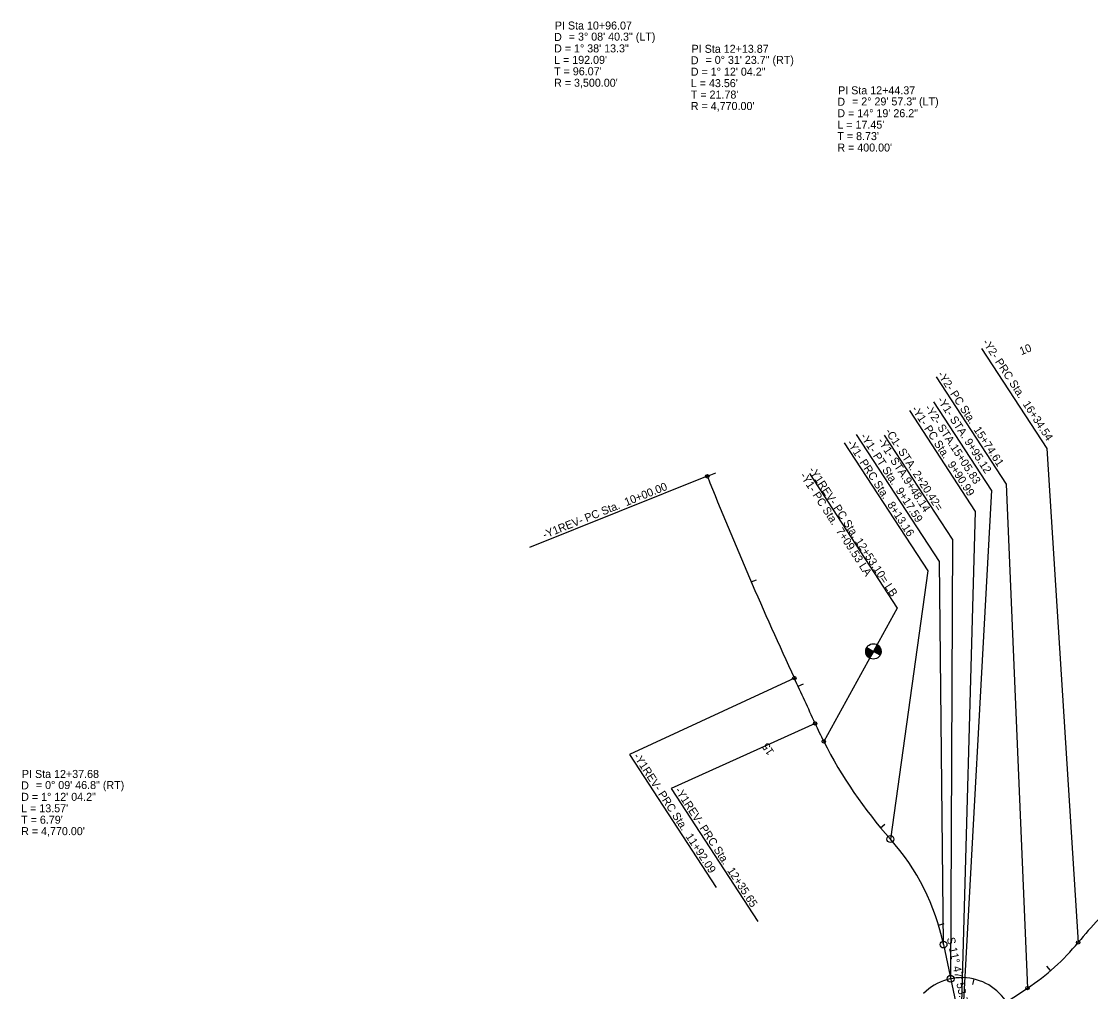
# Model space of a CAD drawing. Extents: x 1636713 to 1642889, y 841520 to 844630.
# Drawn here: x 1639556 to 1640491, y 843782 to 844630 of the extents above; entities that cross this region are included whole.
import ezdxf

# ---------------------------------------------------------------- set-up
doc = ezdxf.new("R2010")
doc.units = 0
for name, color, linetype in [('Exist 4 AWG with gnd feeder circuit in conduit', 7, 'Continuous'), ('Exist 6 AWG with gnd feeder circuit', 7, 'Continuous'), ('Exist 8 AWG with gnd feeder circuit', 7, 'Continuous'), ('Exist 8 AWG with gnd feeder circuit in conduit', 7, 'Continuous'), ('Prop 2 AWG with gnd feeder circuit', 7, 'Continuous'), ('Prop 2 AWG with gnd feeder circuit in conduit', 7, 'Continuous'), ('Prop 4 AWG with gnd feeder circuit', 7, 'Continuous')]:
    doc.layers.add(name, color=color, linetype=linetype)

msp = doc.modelspace()

# ---------------------------------------------------------------- linework, layer by layer
at = {"layer": 'Exist 6 AWG with gnd feeder circuit'}
for p, q in [((1640403.98, 844219.86), (1640353.54, 844297.16)), ((1640369.83, 844176.94), (1640310.39, 844268.03)), ((1640452.2, 844256.33), (1640479.68, 843824.55)), ((1640156.87, 844232.52), (1639999.85, 844169.86)), ((1640416.67, 844225.16), (1640435.28, 843784.64)), ((1640172.29, 844191.74), (1640171.89, 844191.57)), ((1640321.54, 844116.76), (1640257.23, 844000.27)), ((1640300.64, 844078.91), (1640303.93, 844084.77)), ((1640294.79, 844082.19), (1640300.64, 844078.91)), ((1640297.35, 844073.06), (1640300.64, 844078.91)), ((1640300.64, 844078.91), (1640297.35, 844073.06)), ((1640306.5, 844075.63), (1640300.64, 844078.91)), ((1640231.52, 844055.59), (1640087.52, 843988.76)), ((1640249.68, 844016), (1640123.85, 843958.99)), ((1640087.52, 843988.76), (1640163.31, 843872.62)), ((1640123.85, 843958.99), (1640199.63, 843842.85))]:
    msp.add_line(p, q, dxfattribs=at)
for points in [[(1640395.16, 844343.74), (1640452.2, 844256.33)], [(1640355.51, 844318.88), (1640416.67, 844225.16)], [(1640332.21, 844289.39), (1640389.67, 844201.32)], [(1640275.09, 844261.21), (1640348.12, 844149.28), (1640315.45, 843914.9)], [(1640358.34, 844157.37), (1640285.75, 844268.61)], [(1640244.71, 844234.49), (1640321.54, 844116.76)], [(1640403.98, 844219.86), (1640377.83, 843746.81)], [(1640389.67, 844201.32), (1640376.95, 843750.85)], [(1640369.83, 844176.94), (1640368.18, 843792.8)], [(1640361.94, 843822.7), (1640358.34, 844157.37)], [(1640303.98, 844084.74), (1640303.98, 844084.74), (1640300.7, 844078.88)], [(1640304.1, 844084.67), (1640300.81, 844078.82)], [(1640304.21, 844084.6), (1640300.93, 844078.75)], [(1640304.32, 844084.53), (1640301.05, 844078.69)], [(1640304.43, 844084.45), (1640301.16, 844078.62)], [(1640304.54, 844084.37), (1640301.28, 844078.55)], [(1640304.65, 844084.29), (1640301.4, 844078.49)], [(1640304.76, 844084.22), (1640301.52, 844078.42)], [(1640304.87, 844084.14), (1640301.63, 844078.36)], [(1640304.97, 844084.05), (1640301.75, 844078.29)], [(1640305.08, 844083.95), (1640301.87, 844078.23)], [(1640305.18, 844083.86), (1640301.98, 844078.16)], [(1640305.28, 844083.77), (1640302.1, 844078.1)], [(1640305.38, 844083.67), (1640302.22, 844078.03)], [(1640305.48, 844083.57), (1640302.34, 844077.96)], [(1640305.57, 844083.47), (1640302.45, 844077.9)], [(1640305.67, 844083.36), (1640302.57, 844077.83)], [(1640305.77, 844083.26), (1640302.69, 844077.77)], [(1640305.85, 844083.14), (1640302.8, 844077.7)], [(1640305.94, 844083.02), (1640302.92, 844077.64)], [(1640306.03, 844082.91), (1640303.04, 844077.57)], [(1640306.12, 844082.79), (1640303.16, 844077.5)], [(1640306.21, 844082.67), (1640303.27, 844077.44)], [(1640306.29, 844082.54), (1640303.39, 844077.37)], [(1640295.4, 844081.85), (1640293.93, 844079.24)], [(1640295.52, 844081.79), (1640293.93, 844078.95)], [(1640295.63, 844081.72), (1640293.93, 844078.67)], [(1640295.75, 844081.65), (1640293.94, 844078.43)], [(1640295.28, 844081.92), (1640293.95, 844079.55)], [(1640295.87, 844081.59), (1640293.96, 844078.19)], [(1640295.16, 844081.98), (1640293.99, 844079.89)], [(1640295.98, 844081.52), (1640293.99, 844077.97)], [(1640296.1, 844081.46), (1640294.03, 844077.76)], [(1640295.05, 844082.05), (1640294.07, 844080.3)], [(1640296.22, 844081.39), (1640294.07, 844077.55)], [(1640296.34, 844081.33), (1640294.11, 844077.36)], [(1640296.45, 844081.26), (1640294.16, 844077.16)], [(1640294.93, 844082.11), (1640294.19, 844080.79)], [(1640296.57, 844081.19), (1640294.21, 844076.98)], [(1640296.69, 844081.13), (1640294.27, 844076.81)], [(1640296.8, 844081.06), (1640294.32, 844076.64)], [(1640296.92, 844081), (1640294.38, 844076.47)], [(1640297.04, 844080.93), (1640294.45, 844076.31)], [(1640294.81, 844082.18), (1640294.46, 844081.54)], [(1640297.16, 844080.87), (1640294.52, 844076.16)], [(1640297.27, 844080.8), (1640294.59, 844076.01)], [(1640297.39, 844080.74), (1640294.66, 844075.87)], [(1640297.51, 844080.67), (1640294.74, 844075.72)], [(1640297.62, 844080.6), (1640294.81, 844075.58)], [(1640297.74, 844080.54), (1640294.89, 844075.45)], [(1640297.86, 844080.47), (1640294.97, 844075.32)], [(1640297.98, 844080.41), (1640295.05, 844075.19)], [(1640298.09, 844080.34), (1640295.14, 844075.07)], [(1640298.21, 844080.28), (1640295.23, 844074.95)], [(1640298.33, 844080.21), (1640295.32, 844074.83)], [(1640298.44, 844080.14), (1640295.4, 844074.72)], [(1640298.56, 844080.08), (1640295.49, 844074.6)], [(1640298.68, 844080.01), (1640295.59, 844074.5)], [(1640298.8, 844079.95), (1640295.68, 844074.39)], [(1640298.91, 844079.88), (1640295.78, 844074.29)], [(1640299.03, 844079.82), (1640295.88, 844074.19)], [(1640299.15, 844079.75), (1640295.97, 844074.09)], [(1640299.26, 844079.69), (1640296.08, 844074)], [(1640299.38, 844079.62), (1640296.18, 844073.91)], [(1640299.5, 844079.55), (1640296.28, 844073.81)], [(1640299.62, 844079.49), (1640296.38, 844073.72)], [(1640299.73, 844079.42), (1640296.49, 844073.64)], [(1640299.85, 844079.36), (1640296.6, 844073.55)], [(1640299.97, 844079.29), (1640296.71, 844073.47)], [(1640300.08, 844079.23), (1640296.82, 844073.4)], [(1640300.2, 844079.16), (1640296.93, 844073.32)], [(1640300.32, 844079.09), (1640297.04, 844073.25)], [(1640300.44, 844079.03), (1640297.15, 844073.17)], [(1640300.55, 844078.96), (1640297.27, 844073.11), (1640297.27, 844073.11)], [(1640306.37, 844082.41), (1640303.51, 844077.31)], [(1640306.45, 844082.28), (1640303.62, 844077.24)], [(1640306.53, 844082.15), (1640303.74, 844077.18)], [(1640306.6, 844082), (1640303.86, 844077.11)], [(1640306.67, 844081.86), (1640303.98, 844077.04)], [(1640306.74, 844081.7), (1640304.09, 844076.98)], [(1640306.81, 844081.56), (1640304.21, 844076.91)], [(1640306.88, 844081.4), (1640304.33, 844076.85)], [(1640306.94, 844081.23), (1640304.44, 844076.78)], [(1640307, 844081.06), (1640304.56, 844076.72)], [(1640307.06, 844080.89), (1640304.68, 844076.65)], [(1640307.11, 844080.71), (1640304.8, 844076.59)], [(1640307.16, 844080.53), (1640304.91, 844076.52)], [(1640307.2, 844080.33), (1640305.03, 844076.45)], [(1640307.24, 844080.12), (1640305.15, 844076.39)], [(1640307.28, 844079.92), (1640305.26, 844076.32)], [(1640307.31, 844079.69), (1640305.38, 844076.26)], [(1640307.33, 844079.46), (1640305.5, 844076.19)], [(1640307.34, 844079.21), (1640305.62, 844076.13)], [(1640307.35, 844078.95), (1640305.73, 844076.06)], [(1640307.35, 844078.68), (1640305.85, 844075.99)], [(1640307.33, 844078.36), (1640305.97, 844075.93)], [(1640307.29, 844078.02), (1640306.08, 844075.86)], [(1640307.23, 844077.63), (1640306.2, 844075.8)], [(1640307.12, 844077.16), (1640306.32, 844075.73)], [(1640306.9, 844076.5), (1640306.44, 844075.67)]]:
    msp.add_lwpolyline(points, dxfattribs=at)
for centre, radius in [((1640155.48, 844231.96), 1.5), ((1640300.64, 844078.92), 6.71), ((1640231.52, 844055.59), 1.5), ((1640249.68, 844016), 1.5), ((1640257.23, 844000.27), 1.5), ((1640315.45, 843914.9), 3), ((1640361.94, 843822.7), 3), ((1640479.68, 843824.55), 1.5), ((1640368.18, 843792.8), 3), ((1640435.28, 843784.64), 1.5)]:
    msp.add_circle(centre, radius, dxfattribs=at)
for start, end in [(330.72648, 60.72648), (150.72648, 240.72648)]:
    msp.add_arc((1640300.64, 844078.92), 6.71, start, end, dxfattribs=at)
at = {"layer": 'Exist 8 AWG with gnd feeder circuit'}
for p, q in [((1640361.94, 843822.7), (1640376.95, 843750.85)), ((1640335.17, 843718.72), (1640435.28, 843784.64))]:
    msp.add_line(p, q, dxfattribs=at)
for centre, radius, start, end in [((1643406.26, 845529.05), 3500, 201.75249, 204.89701), ((1635904.82, 842047.48), 4770, 24.37377, 24.89701), ((1640614.03, 844181.07), 400, 204.37377, 206.87302), ((1640614.03, 844181.07), 400, 206.87302, 221.71629), ((1640166.16, 843781.81), 200, 11.79824, 41.71629), ((1640788.47, 843570.29), 400, 132.72767, 140.53191), ((1640325.29, 843951.68), 200, 303.36513, 320.53191), ((1640377.79, 843746.79), 47, 20.39794, 135)]:
    msp.add_arc(centre, radius, start, end, dxfattribs=at)
at = {"layer": 'Prop 2 AWG with gnd feeder circuit in conduit'}
msp.add_line((1640155.48, 844231.96), (1640162.91, 844234.93), dxfattribs=at)
at = {"layer": 'Prop 4 AWG with gnd feeder circuit'}
for p, q in [((1640193.86, 844139.62), (1640198.45, 844141.61)), ((1640234.85, 844048.42), (1640239.39, 844050.51)), ((1640306.86, 843924.86), (1640310.7, 843928.06)), ((1640357.59, 843839.74), (1640362.37, 843841.19)), ((1640455.54, 843799.91), (1640452.28, 843803.71)), ((1640388.44, 843792.57), (1640387.31, 843787.7))]:
    msp.add_line(p, q, dxfattribs=at)

# ---------------------------------------------------------------- texts
at = {"layer": 'Exist 4 AWG with gnd feeder circuit in conduit'}
for s, rotation, p in [('10', 21.75249, (1640429.97, 844337.72)), ('15', 123.36513, (1640214.16, 843991.13))]:
    msp.add_text(s, height=7, rotation=rotation, dxfattribs=at).set_placement(p)
at = {"layer": 'Exist 6 AWG with gnd feeder circuit'}
for s, rotation, p in [('-Y2- PRC Sta.  16+34.54', 303.12591, (1640395.64, 844349.11)), ('-Y2- PC Sta.  15+74.61', 303.12591, (1640356.33, 844321.11)), ('-Y1- STA. 9+95.12', 303.12591, (1640356.05, 844298.8)), ('-Y1- PC Sta.  9+90.99', 303.12591, (1640333.61, 844290.73)), ('-Y2- STA.15+05.83', 303.12591, (1640345.17, 844291.7)), ('-C1- STA. 2+20.42=', 303.12591, (1640310.54, 844271.11)), ('-Y1- PRC Sta.  8+13.16', 303.12591, (1640277.15, 844261.1)), ('-Y1- PT Sta.  9+17.59', 303.12591, (1640288.9, 844266.89)), ('-Y1- STA.9+48.14', 303.12591, (1640303.94, 844262.84)), ('-Y1- PC Sta.  7+09.53 LA', 303.12591, (1640236.11, 844232.57)), ('-Y1REV- PC Sta. 12+53.10= LB', 303.12591, (1640243.65, 844237.49)), ('-Y1REV- PC Sta.  10+00.00', 21.75249, (1640013.13, 844177.32)), ('-Y1REV- PRC Sta.  11+92.09', 303.12591, (1640090.44, 843987.34)), ('-Y1REV- PRC Sta.  12+35.65', 303.12591, (1640126.77, 843957.57))]:
    msp.add_text(s, height=7, rotation=rotation, dxfattribs=at).set_placement(p)
at = {"layer": 'Exist 8 AWG with gnd feeder circuit in conduit'}
msp.add_text('S 11%%d 47\' 53.7" E', height=7, rotation=281.79824, dxfattribs=at).set_placement((1640364.85, 843828.28))
at = {"layer": 'Prop 2 AWG with gnd feeder circuit'}
for s, p in [('PI Sta 10+96.07', (1640022.14, 844622.44)), ('D', (1640021.47, 844612.44)), ('= 3%%d 08\' 40.3" (LT)', (1640034.32, 844612.74)), ('D = 1%%d 38\' 13.3"', (1640021.47, 844602.44)), ('PI Sta 12+13.87', (1640141.68, 844602.09)), ("L = 192.09'", (1640021.47, 844592.44)), ('D', (1640141, 844592.09)), ('= 0%%d 31\' 23.7" (RT)', (1640153.85, 844592.39)), ("T = 96.07'", (1640021.47, 844582.44)), ('D = 1%%d 12\' 04.2"', (1640141, 844582.09)), ("R = 3,500.00'", (1640021.47, 844572.44)), ("L = 43.56'", (1640141, 844572.09)), ("T = 21.78'", (1640141, 844562.09)), ('PI Sta 12+44.37', (1640269.79, 844565.8)), ("R = 4,770.00'", (1640141, 844552.09)), ('D', (1640269.11, 844555.8)), ('= 2%%d 29\' 57.3" (LT)', (1640281.96, 844556.1)), ('D = 14%%d 19\' 26.2"', (1640269.11, 844545.8)), ("L = 17.45'", (1640269.11, 844535.8)), ("T = 8.73'", (1640269.11, 844525.8)), ("R = 400.00'", (1640269.11, 844515.8)), ('PI Sta 12+37.68', (1639556.24, 843968.32)), ('D', (1639555.57, 843958.32)), ('= 0%%d 09\' 46.8" (RT)', (1639568.42, 843958.62)), ('D = 1%%d 12\' 04.2"', (1639555.57, 843948.32)), ("L = 13.57'", (1639555.57, 843938.32)), ("T = 6.79'", (1639555.57, 843928.32)), ("R = 4,770.00'", (1639555.57, 843918.32))]:
    msp.add_text(s, height=7, dxfattribs=at).set_placement(p)

doc.saveas('drawing.dxf')
